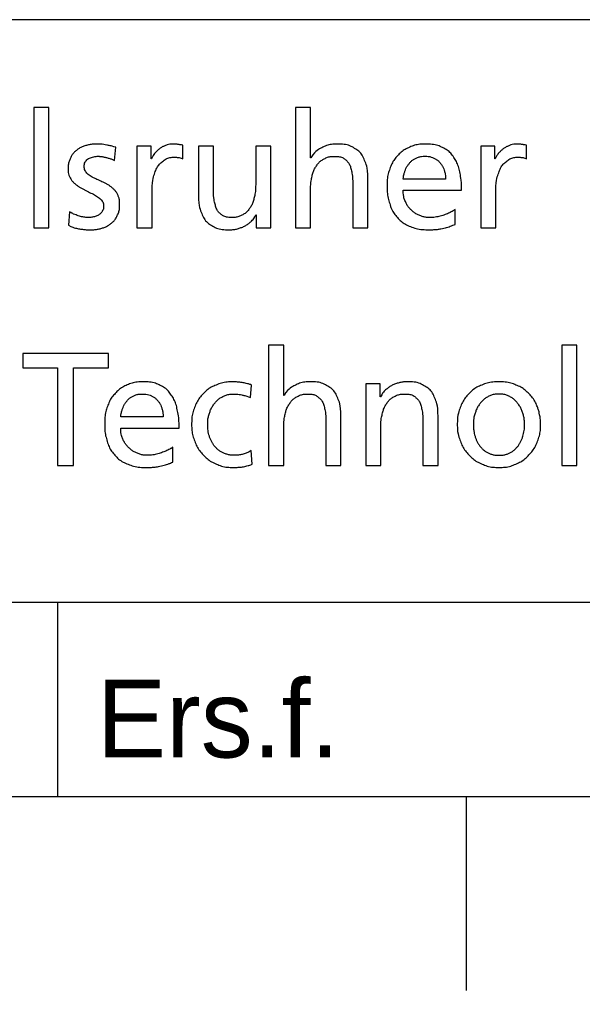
# Model space of a CAD drawing. Extents: x 0 to 395, y 0 to 270.
# Drawn here: x 136.01 to 150.5, y 0 to 25 of the extents above; entities that cross this region are included whole.
import ezdxf

# ---------------------------------------------------------------- set-up
doc = ezdxf.new("R2010")
doc.units = 0
doc.layers.add('90_Plankopf', color=7, linetype='Continuous')

msp = doc.modelspace()

# ---------------------------------------------------------------- linework, layer by layer
at = {"layer": '90_Plankopf'}
for p, q in [((5, 25), (390, 25)), ((140.21, 21.414), (140.21, 21.761)), ((149.056, 21.414), (149.056, 21.761)), ((138.456, 21.369), (138.489, 21.708)), ((146.971, 20.89), (145.882, 20.89)), ((145.882, 20.602), (147.384, 20.602)), ((137.296, 20.048), (137.276, 19.702)), ((147.223, 19.723), (147.223, 20.11)), ((141.95, 15.266), (141.983, 15.588)), ((139.705, 14.771), (138.615, 14.771)), ((138.615, 14.482), (140.118, 14.482)), ((139.957, 13.603), (139.957, 13.991)), ((142, 13.553), (141.971, 13.9)), ((100, 10), (225, 10)), ((137, 5), (137, 10)), ((5, 5), (390, 5)), ((147.5, 5), (147.5, 0))]:
    msp.add_line(p, q, dxfattribs=at)
for points in [[(136.38, 19.636), (136.767, 19.636), (136.767, 22.731), (136.38, 22.731), (136.38, 19.636)], [(143.508, 21.439), (143.5, 21.439), (143.5, 22.731), (143.112, 22.731), (143.112, 19.636), (143.5, 19.636), (143.5, 20.61)], [(139.406, 21.414), (139.397, 21.414), (139.397, 21.74), (139.034, 21.74), (139.034, 19.636), (139.422, 19.636), (139.422, 20.593)], [(141.003, 20.651), (141.003, 21.74), (140.615, 21.74), (140.615, 20.49)], [(142.092, 19.97), (142.101, 19.97), (142.101, 19.636), (142.476, 19.636), (142.476, 21.74), (142.088, 21.74), (142.088, 20.766)], [(148.251, 21.414), (148.243, 21.414), (148.243, 21.74), (147.88, 21.74), (147.88, 19.636), (148.268, 19.636), (148.268, 20.593)], [(144.586, 20.725), (144.586, 19.636), (144.973, 19.636), (144.973, 20.886)], [(142.817, 15.32), (142.809, 15.32), (142.809, 16.611), (142.421, 16.611), (142.421, 13.516), (142.809, 13.516), (142.809, 14.49)], [(149.962, 13.516), (150.35, 13.516), (150.35, 16.611), (149.962, 16.611), (149.962, 13.516)], [(136.989, 13.516), (137.402, 13.516), (137.402, 16.034), (138.297, 16.034), (138.297, 16.397), (136.093, 16.397), (136.093, 16.034), (136.989, 16.034), (136.989, 13.516)], [(145.302, 15.287), (145.294, 15.287), (145.294, 15.621), (144.918, 15.621), (144.918, 13.516), (145.306, 13.516), (145.306, 14.49)], [(143.894, 14.606), (143.894, 13.516), (144.282, 13.516), (144.282, 14.767)], [(146.392, 14.606), (146.392, 13.516), (146.779, 13.516), (146.779, 14.767)]]:
    msp.add_lwpolyline(points, dxfattribs=at)
for points in [[(138.489, 21.708), (138.413, 21.731), (138.336, 21.75), (138.258, 21.766), (138.18, 21.781), (138.096, 21.789), (138.006, 21.79), (137.902, 21.79), (137.804, 21.777), (137.715, 21.75), (137.624, 21.724), (137.546, 21.683), (137.479, 21.63), (137.411, 21.577), (137.358, 21.509), (137.321, 21.428), (137.283, 21.347), (137.264, 21.251), (137.263, 21.142), (137.264, 21.058), (137.281, 20.986), (137.314, 20.924), (137.346, 20.863), (137.39, 20.81), (137.444, 20.764), (137.499, 20.72), (137.558, 20.68), (137.622, 20.645), (137.687, 20.61), (137.752, 20.577), (137.816, 20.547), (137.881, 20.516), (137.941, 20.485), (137.994, 20.452), (138.049, 20.42), (138.092, 20.384), (138.125, 20.343), (138.157, 20.303), (138.175, 20.255), (138.175, 20.201), (138.175, 20.145), (138.162, 20.097), (138.138, 20.058), (138.115, 20.02), (138.083, 19.989), (138.044, 19.965), (138.005, 19.942), (137.962, 19.925), (137.916, 19.915), (137.87, 19.905), (137.824, 19.9), (137.779, 19.9), (137.741, 19.9), (137.694, 19.905), (137.638, 19.916), (137.583, 19.927), (137.525, 19.944), (137.465, 19.966), (137.404, 19.988), (137.349, 20.015), (137.296, 20.048)], [(140.21, 21.761), (140.183, 21.767), (140.157, 21.771), (140.133, 21.776), (140.109, 21.78), (140.082, 21.784), (140.053, 21.786), (140.025, 21.789), (139.992, 21.79), (139.954, 21.79), (139.879, 21.789), (139.807, 21.773), (139.736, 21.741), (139.666, 21.709), (139.602, 21.666), (139.545, 21.609), (139.487, 21.553), (139.441, 21.488), (139.406, 21.414)], [(144.973, 20.886), (144.974, 21.075), (144.946, 21.237), (144.89, 21.372), (144.835, 21.507), (144.748, 21.61), (144.632, 21.681), (144.515, 21.753), (144.367, 21.789), (144.185, 21.79), (144.037, 21.789), (143.906, 21.759), (143.79, 21.698), (143.674, 21.638), (143.58, 21.551), (143.508, 21.439)], [(147.384, 20.602), (147.385, 20.771), (147.369, 20.929), (147.338, 21.073), (147.306, 21.217), (147.255, 21.342), (147.183, 21.449), (147.111, 21.557), (147.016, 21.64), (146.897, 21.699), (146.778, 21.759), (146.63, 21.789), (146.456, 21.79), (146.306, 21.789), (146.172, 21.763), (146.05, 21.712), (145.93, 21.659), (145.826, 21.586), (145.74, 21.491), (145.653, 21.397), (145.586, 21.285), (145.54, 21.154), (145.493, 21.025), (145.47, 20.882), (145.469, 20.725), (145.469, 20.553), (145.491, 20.398), (145.535, 20.258), (145.578, 20.118), (145.645, 19.999), (145.734, 19.899), (145.824, 19.799), (145.936, 19.722), (146.073, 19.668), (146.211, 19.614), (146.372, 19.587), (146.559, 19.586), (146.674, 19.587), (146.771, 19.595), (146.852, 19.61), (146.933, 19.625), (147.003, 19.643), (147.062, 19.663), (147.121, 19.684), (147.174, 19.704), (147.223, 19.723)], [(149.056, 21.761), (149.029, 21.767), (149.003, 21.771), (148.979, 21.776), (148.954, 21.78), (148.927, 21.784), (148.899, 21.786), (148.871, 21.789), (148.838, 21.79), (148.8, 21.79), (148.725, 21.789), (148.652, 21.773), (148.581, 21.741), (148.511, 21.709), (148.447, 21.666), (148.39, 21.609), (148.332, 21.553), (148.286, 21.488), (148.251, 21.414)], [(137.276, 19.702), (137.365, 19.656), (137.459, 19.624), (137.557, 19.608), (137.655, 19.592), (137.754, 19.585), (137.853, 19.586), (137.948, 19.586), (138.039, 19.599), (138.126, 19.625), (138.214, 19.652), (138.292, 19.692), (138.362, 19.746), (138.43, 19.799), (138.486, 19.868), (138.526, 19.95), (138.567, 20.033), (138.587, 20.13), (138.588, 20.242), (138.587, 20.338), (138.57, 20.419), (138.538, 20.486), (138.505, 20.552), (138.461, 20.609), (138.407, 20.656), (138.353, 20.702), (138.294, 20.741), (138.229, 20.775), (138.164, 20.808), (138.1, 20.839), (138.035, 20.867), (137.97, 20.896), (137.911, 20.925), (137.857, 20.956), (137.803, 20.988), (137.759, 21.025), (137.726, 21.066), (137.694, 21.109), (137.677, 21.16), (137.676, 21.221), (137.677, 21.278), (137.695, 21.326), (137.728, 21.364), (137.762, 21.402), (137.807, 21.43), (137.863, 21.449), (137.919, 21.468), (137.981, 21.476), (138.047, 21.476), (138.071, 21.476), (138.101, 21.473), (138.138, 21.468), (138.174, 21.461), (138.212, 21.453), (138.253, 21.443), (138.294, 21.433), (138.332, 21.421), (138.368, 21.408), (138.404, 21.396), (138.433, 21.383), (138.456, 21.369)], [(139.422, 20.593), (139.423, 20.77), (139.447, 20.923), (139.494, 21.051), (139.541, 21.179), (139.607, 21.278), (139.693, 21.346), (139.778, 21.416), (139.879, 21.451), (139.996, 21.451), (140.029, 21.452), (140.064, 21.449), (140.102, 21.444), (140.139, 21.439), (140.174, 21.429), (140.21, 21.414)], [(143.5, 20.61), (143.5, 20.738), (143.513, 20.855), (143.538, 20.961), (143.564, 21.067), (143.602, 21.158), (143.654, 21.235), (143.707, 21.312), (143.773, 21.371), (143.854, 21.413), (143.934, 21.455), (144.03, 21.476), (144.14, 21.476), (144.252, 21.47), (144.341, 21.439), (144.406, 21.381), (144.472, 21.325), (144.518, 21.242), (144.545, 21.134), (144.573, 21.025), (144.586, 20.889), (144.586, 20.725)], [(145.882, 20.89), (145.889, 20.959), (145.905, 21.028), (145.929, 21.097), (145.953, 21.165), (145.988, 21.228), (146.033, 21.286), (146.078, 21.343), (146.134, 21.388), (146.203, 21.423), (146.271, 21.458), (146.352, 21.476), (146.447, 21.476), (146.531, 21.476), (146.605, 21.46), (146.67, 21.43), (146.736, 21.4), (146.79, 21.358), (146.835, 21.304), (146.879, 21.251), (146.914, 21.188), (146.936, 21.118), (146.96, 21.047), (146.971, 20.972), (146.971, 20.89)], [(148.268, 20.593), (148.268, 20.77), (148.292, 20.923), (148.339, 21.051), (148.387, 21.179), (148.453, 21.278), (148.539, 21.346), (148.624, 21.416), (148.725, 21.451), (148.841, 21.451), (148.875, 21.452), (148.91, 21.449), (148.947, 21.444), (148.984, 21.439), (149.02, 21.429), (149.056, 21.414)], [(142.088, 20.766), (142.088, 20.638), (142.076, 20.521), (142.05, 20.415), (142.025, 20.309), (141.987, 20.218), (141.934, 20.141), (141.882, 20.064), (141.815, 20.005), (141.735, 19.963), (141.654, 19.921), (141.559, 19.9), (141.449, 19.9), (141.337, 19.907), (141.248, 19.938), (141.183, 19.995), (141.117, 20.051), (141.071, 20.134), (141.044, 20.242), (141.015, 20.351), (141.002, 20.487), (141.003, 20.651)], [(147.223, 20.11), (147.199, 20.09), (147.164, 20.068), (147.118, 20.044), (147.072, 20.02), (147.02, 19.998), (146.96, 19.975), (146.9, 19.953), (146.837, 19.936), (146.771, 19.922), (146.705, 19.908), (146.64, 19.9), (146.575, 19.9), (146.482, 19.9), (146.395, 19.917), (146.312, 19.951), (146.229, 19.984), (146.155, 20.033), (146.091, 20.095), (146.026, 20.157), (145.975, 20.23), (145.938, 20.316), (145.902, 20.402), (145.883, 20.497), (145.882, 20.602)], [(140.615, 20.49), (140.615, 20.301), (140.643, 20.139), (140.698, 20.004), (140.754, 19.869), (140.841, 19.766), (140.957, 19.695), (141.073, 19.623), (141.223, 19.587), (141.403, 19.586), (141.502, 19.587), (141.597, 19.602), (141.687, 19.632), (141.777, 19.663), (141.857, 19.707), (141.928, 19.764), (141.998, 19.821), (142.053, 19.89), (142.092, 19.97)], [(140.118, 14.482), (140.118, 14.652), (140.102, 14.81), (140.071, 14.953), (140.04, 15.098), (139.988, 15.223), (139.917, 15.33), (139.845, 15.437), (139.75, 15.521), (139.63, 15.58), (139.511, 15.639), (139.364, 15.67), (139.189, 15.67), (139.04, 15.67), (138.905, 15.644), (138.784, 15.592), (138.664, 15.54), (138.56, 15.467), (138.473, 15.372), (138.386, 15.277), (138.32, 15.165), (138.274, 15.035), (138.227, 14.906), (138.204, 14.763), (138.203, 14.606), (138.203, 14.434), (138.224, 14.278), (138.268, 14.139), (138.311, 13.999), (138.378, 13.88), (138.468, 13.78), (138.557, 13.679), (138.67, 13.602), (138.807, 13.549), (138.944, 13.494), (139.106, 13.468), (139.292, 13.467), (139.407, 13.468), (139.505, 13.475), (139.586, 13.49), (139.666, 13.505), (139.736, 13.523), (139.796, 13.544), (139.854, 13.564), (139.908, 13.584), (139.957, 13.603)], [(141.983, 15.588), (141.945, 15.603), (141.9, 15.617), (141.847, 15.63), (141.794, 15.642), (141.738, 15.652), (141.68, 15.659), (141.621, 15.667), (141.566, 15.67), (141.513, 15.67), (141.351, 15.67), (141.205, 15.642), (141.073, 15.589), (140.942, 15.535), (140.829, 15.458), (140.735, 15.36), (140.641, 15.261), (140.568, 15.145), (140.517, 15.011), (140.466, 14.877), (140.441, 14.73), (140.44, 14.569), (140.441, 14.418), (140.467, 14.275), (140.518, 14.142), (140.57, 14.009), (140.643, 13.893), (140.738, 13.792), (140.833, 13.691), (140.946, 13.611), (141.077, 13.554), (141.208, 13.497), (141.353, 13.468), (141.513, 13.467), (141.56, 13.467), (141.611, 13.469), (141.666, 13.473), (141.721, 13.477), (141.776, 13.485), (141.833, 13.498), (141.89, 13.511), (141.945, 13.529), (142, 13.553)], [(144.282, 14.767), (144.283, 14.956), (144.255, 15.118), (144.199, 15.253), (144.143, 15.387), (144.057, 15.49), (143.941, 15.562), (143.824, 15.634), (143.676, 15.67), (143.494, 15.67), (143.346, 15.67), (143.215, 15.639), (143.099, 15.579), (142.982, 15.519), (142.889, 15.432), (142.817, 15.32)], [(146.779, 14.767), (146.78, 14.956), (146.752, 15.118), (146.696, 15.253), (146.641, 15.387), (146.554, 15.49), (146.438, 15.562), (146.322, 15.634), (146.173, 15.67), (145.991, 15.67), (145.893, 15.67), (145.798, 15.655), (145.708, 15.625), (145.618, 15.594), (145.537, 15.55), (145.467, 15.492), (145.397, 15.435), (145.341, 15.367), (145.302, 15.287)], [(149.394, 14.821), (149.381, 14.887), (149.363, 14.95), (149.34, 15.011), (149.289, 15.145), (149.217, 15.261), (149.123, 15.36), (149.028, 15.458), (148.916, 15.535), (148.785, 15.589), (148.654, 15.642), (148.509, 15.67), (148.348, 15.67), (148.187, 15.67), (148.04, 15.642), (147.909, 15.589), (147.777, 15.535), (147.665, 15.458), (147.57, 15.36), (147.476, 15.261), (147.403, 15.145), (147.352, 15.011), (147.301, 14.877), (147.276, 14.73), (147.275, 14.569)], [(138.615, 14.771), (138.622, 14.84), (138.638, 14.908), (138.663, 14.977), (138.687, 15.046), (138.721, 15.109), (138.767, 15.166), (138.811, 15.224), (138.868, 15.269), (138.936, 15.304), (139.005, 15.338), (139.086, 15.356), (139.181, 15.357), (139.265, 15.356), (139.339, 15.341), (139.403, 15.311), (139.469, 15.28), (139.523, 15.239), (139.568, 15.185), (139.613, 15.131), (139.647, 15.069), (139.67, 14.999), (139.693, 14.928), (139.705, 14.852), (139.705, 14.771)], [(141.971, 13.9), (141.931, 13.874), (141.886, 13.852), (141.839, 13.834), (141.792, 13.816), (141.743, 13.803), (141.694, 13.794), (141.646, 13.785), (141.599, 13.78), (141.554, 13.78), (141.455, 13.781), (141.366, 13.796), (141.289, 13.827), (141.213, 13.856), (141.147, 13.897), (141.091, 13.95), (141.036, 14.002), (140.991, 14.062), (140.956, 14.129), (140.92, 14.197), (140.895, 14.267), (140.877, 14.342), (140.861, 14.418), (140.853, 14.493), (140.853, 14.569), (140.853, 14.67), (140.867, 14.768), (140.897, 14.861), (140.927, 14.955), (140.971, 15.039), (141.029, 15.113), (141.086, 15.188), (141.156, 15.247), (141.24, 15.29), (141.324, 15.333), (141.421, 15.356), (141.529, 15.357), (141.592, 15.357), (141.659, 15.35), (141.73, 15.335), (141.802, 15.32), (141.875, 15.297), (141.95, 15.266)], [(142.809, 14.49), (142.809, 14.619), (142.822, 14.736), (142.847, 14.842), (142.872, 14.948), (142.911, 15.039), (142.963, 15.115), (143.015, 15.193), (143.082, 15.252), (143.163, 15.294), (143.243, 15.336), (143.339, 15.356), (143.449, 15.357), (143.561, 15.35), (143.65, 15.319), (143.715, 15.262), (143.78, 15.206), (143.826, 15.123), (143.854, 15.014), (143.882, 14.906), (143.895, 14.77), (143.894, 14.606)], [(145.306, 14.49), (145.306, 14.619), (145.319, 14.736), (145.344, 14.842), (145.37, 14.948), (145.408, 15.039), (145.46, 15.115), (145.513, 15.193), (145.579, 15.252), (145.66, 15.294), (145.74, 15.336), (145.836, 15.356), (145.946, 15.357), (146.058, 15.35), (146.147, 15.319), (146.212, 15.262), (146.277, 15.206), (146.324, 15.123), (146.351, 15.014), (146.379, 14.906), (146.392, 14.77), (146.392, 14.606)], [(147.688, 14.569), (147.688, 14.67), (147.703, 14.768), (147.733, 14.861), (147.762, 14.955), (147.805, 15.039), (147.862, 15.113), (147.918, 15.188), (147.988, 15.247), (148.069, 15.29), (148.151, 15.333), (148.244, 15.356), (148.348, 15.357), (148.451, 15.356), (148.543, 15.333), (148.625, 15.29), (148.706, 15.247), (148.775, 15.188), (148.831, 15.113), (148.887, 15.039), (148.931, 14.955), (148.96, 14.861), (148.989, 14.768), (149.004, 14.67), (149.004, 14.569), (149.004, 14.493), (148.996, 14.418), (148.98, 14.342), (148.963, 14.267), (148.938, 14.197), (148.904, 14.129), (148.87, 14.062), (148.828, 14.002), (148.775, 13.95), (148.723, 13.897), (148.662, 13.856), (148.591, 13.827), (148.52, 13.796), (148.439, 13.781), (148.348, 13.78), (148.257, 13.781), (148.175, 13.796), (148.103, 13.827), (148.032, 13.856), (147.97, 13.897), (147.918, 13.95), (147.865, 14.002), (147.823, 14.062), (147.789, 14.129), (147.755, 14.197), (147.729, 14.267), (147.713, 14.342), (147.696, 14.418), (147.688, 14.493), (147.688, 14.569)], [(147.275, 14.569), (147.276, 14.418), (147.302, 14.275), (147.354, 14.142), (147.405, 14.009), (147.478, 13.893), (147.574, 13.792), (147.669, 13.691), (147.781, 13.611), (147.912, 13.554), (148.044, 13.497), (148.189, 13.468), (148.348, 13.467), (148.506, 13.468), (148.652, 13.497), (148.781, 13.554), (148.912, 13.611), (149.025, 13.691), (149.119, 13.792), (149.214, 13.893), (149.287, 14.009), (149.339, 14.142), (149.39, 14.275), (149.416, 14.418), (149.417, 14.569), (149.417, 14.657), (149.409, 14.741), (149.394, 14.821)], [(139.957, 13.991), (139.932, 13.971), (139.898, 13.949), (139.851, 13.925), (139.805, 13.901), (139.753, 13.878), (139.693, 13.856), (139.633, 13.834), (139.571, 13.816), (139.505, 13.802), (139.439, 13.788), (139.373, 13.781), (139.308, 13.78), (139.216, 13.781), (139.129, 13.798), (139.045, 13.832), (138.963, 13.865), (138.888, 13.913), (138.824, 13.975), (138.76, 14.037), (138.709, 14.111), (138.672, 14.197), (138.635, 14.283), (138.616, 14.378), (138.615, 14.482)]]:
    msp.add_open_spline(points, degree=3, dxfattribs=at)

# ---------------------------------------------------------------- texts
msp.add_text('Ers.f.', height=2, dxfattribs=at).set_placement((138, 6))

doc.saveas('drawing.dxf')
